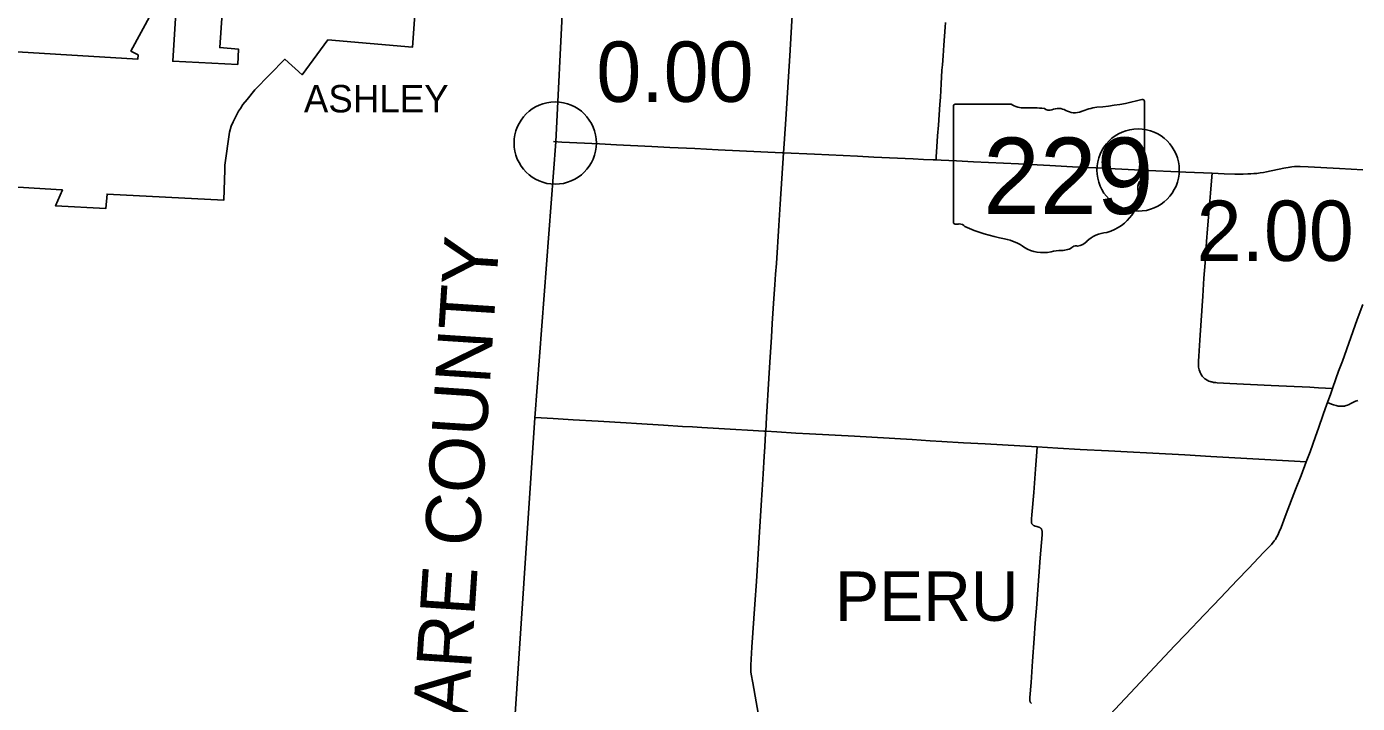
# Model space of a CAD drawing. Extents: x 1813937 to 1948437, y 826606 to 1022856.
# Drawn here: x 1840375 to 1864627, y 867056 to 879389 of the extents above; entities that cross this region are included whole.
import ezdxf

# ---------------------------------------------------------------- set-up
doc = ezdxf.new("R2010")
doc.units = 0
for name, color, linetype in [('Default', 7, 'Continuous'), ('GM_X_Adjacent_County_Text', 7, 'Continuous'), ('GM_X_Corporation', 7, 'Continuous'), ('GM_X_Corporation_Text', 7, 'Continuous'), ('GM_X_County', 7, 'Continuous'), ('GM_X_County_Road', 7, 'Continuous'), ('GM_X_State_Route', 7, 'Continuous'), ('GM_X_State_Shield', 7, 'Continuous'), ('GM_X_Township_Road', 7, 'Continuous'), ('GM_X_Township_Text', 7, 'Continuous')]:
    doc.layers.add(name, color=color, linetype=linetype)

msp = doc.modelspace()

# ---------------------------------------------------------------- linework, layer by layer
at = {"layer": 'Default'}
for centre in [(1850008, 877268), (1850008, 877268), (1860631, 876776)]:
    msp.add_circle(centre, 750, dxfattribs=at)
at = {"layer": 'GM_X_Corporation'}
for points in [[(1839395, 878979), (1842403, 878797), (1842406, 878874), (1842276, 878944), (1843026, 880333)], [(1843137, 880326), (1843037, 878758), (1844222, 878701), (1844237, 878976), (1843894, 879006), (1843983, 880269)], [(1847478, 880034), (1847407, 879013), (1845866, 879149), (1845394, 878513), (1845080, 878796), (1844533, 878238), (1844393, 878064), (1844314, 877970), (1844271, 877898), (1844236, 877846), (1844178, 877730), (1844140, 877653), (1844101, 877578), (1844075, 877468), (1843989, 876865), (1843985, 876781), (1843972, 876227), (1841843, 876336), (1841816, 876073), (1840902, 876121), (1841027, 876414), (1840914, 876421), (1839212, 876522)]]:
    msp.add_lwpolyline(points, dxfattribs=at)
at = {"layer": 'GM_X_County'}
msp.add_lwpolyline([(1849106, 864311), (1849634, 872258), (1850017, 877290), (1850147, 879854), (1845959, 880135), (1842150, 880416), (1839410, 880574)], dxfattribs=at)
at = {"layer": 'GM_X_County_Road'}
for points in [[(1853845, 872014), (1853859, 872274), (1853901, 872979), (1853919, 873274), (1853948, 873731), (1853964, 873978), (1853994, 874436), (1854011, 874682), (1854025, 874878), (1854038, 875075), (1854084, 875763), (1854110, 876156), (1854170, 877091)], [(1864174, 872796), (1864234, 872970), (1864284, 873109), (1864353, 873293), (1864625, 874049), (1864725, 874327)], [(1864084, 872541), (1864143, 872706), (1864174, 872796)], [(1863695, 871458), (1863764, 871641), (1863814, 871779), (1863864, 871918), (1863919, 872073), (1864005, 872320), (1864071, 872506), (1864084, 872541)], [(1853831, 866184), (1853607, 867428), (1853581, 867590), (1853575, 867628), (1853573, 867652), (1853572, 867674), (1853571, 867703), (1853573, 867754), (1853594, 868081), (1853649, 868867), (1853675, 869277), (1853717, 869981), (1853760, 870669), (1853779, 870948), (1853798, 871242), (1853817, 871553), (1853828, 871734), (1853843, 871979), (1853845, 872014)], [(1860116, 866845), (1860675, 867445), (1860843, 867625), (1861293, 868102), (1861498, 868315), (1861837, 868671), (1861996, 868837), (1862132, 868979), (1862437, 869300), (1862641, 869514), (1862923, 869812), (1863059, 869954), (1863111, 870016), (1863132, 870043), (1863148, 870070), (1863161, 870091), (1863176, 870121), (1863203, 870181), (1863235, 870263), (1863312, 870462), (1863441, 870798), (1863501, 870951), (1863602, 871211), (1863695, 871458)]]:
    msp.add_lwpolyline(points, dxfattribs=at)
at = {"layer": 'GM_X_State_Route'}
for points in [[(1849978, 877293), (1850128, 877285), (1850816, 877251), (1851127, 877236), (1851766, 877203), (1852094, 877189), (1852553, 877166), (1852979, 877146), (1854142, 877092), (1854170, 877091), (1854732, 877063), (1855518, 877026), (1855813, 877013), (1856534, 876978), (1856719, 876970)], [(1856719, 876970), (1856895, 876961), (1856952, 876959), (1857042, 876955), (1857321, 876944), (1857632, 876927), (1858451, 876887), (1859025, 876856), (1859434, 876835), (1859860, 876814), (1860450, 876786), (1860679, 876775), (1861499, 876738), (1861978, 876716), (1862196, 876705), (1862395, 876698), (1862473, 876700), (1862543, 876701), (1862632, 876704), (1862686, 876706), (1862740, 876711), (1862796, 876715), (1862854, 876723), (1862916, 876731), (1862968, 876741), (1863289, 876810), (1863401, 876830), (1863435, 876835), (1863483, 876838), (1863519, 876839), (1863581, 876840), (1863728, 876836), (1864301, 876803), (1864727, 876779)]]:
    msp.add_lwpolyline(points, dxfattribs=at)
at = {"layer": 'GM_X_State_Shield'}
for p, q in [((1857265, 877938), (1857265, 875825)), ((1858318, 877975), (1857299, 877975)), ((1860745, 876922), (1860745, 878027)), ((1860745, 876922), (1860745, 876922))]:
    msp.add_line(p, q, dxfattribs=at)
for centre, major_axis, start_param, end_param in [((1857305, 877943), (40.3, 0), 1.712693, 3.28349), ((1858561, 878220), (391, 0), 4.042523, 4.731795), ((1858691, 876788), (1404, 0), 1.404758, 1.657858), ((1859175, 877710), (235, 0), 0.950623, 2.079405), ((1859976, 877329), (743, 0), 1.699011, 2.107814), ((1859505, 880856), (3691, 0), 4.814394, 5.042369), ((1860707, 878032), (38.7, 0), 6.141152, 7.989035), ((1859009, 877954), (113, 0), 3.836095, 5.185415), ((1859478, 878045), (282, 0), 4.081561, 5.145723), ((1860736, 876841), (60, 0), 1.883978, 3.671073), ((1860355, 876701), (360, 0), 5.934695, 6.695948), ((1860704, 876917), (41.5, 0), 5.05454, 6.418171), ((1860884, 876459), (262, 0), 2.387724, 3.262537), ((1859712, 876318), (923, 0), 5.101752, 6.440018), ((1857305, 875821), (40.7, 0), 3.00124, 4.508301), ((1857311, 876037), (310, 0), 4.665946, 4.897461), ((1857375, 875703), (112, 0), 0.519207, 1.627899), ((1858788, 877602), (2665, 0), 4.195997, 4.488961), ((1857993, 874876), (834, 0), 0.823519, 1.323587), ((1860101, 875232), (506, 0), 1.647645, 2.488434), ((1858895, 875693), (529, 0), 4.026481, 4.996735), ((1859201, 874962), (435, 0), 1.495662, 1.94098), ((1859240, 875535), (282, 0), 4.691044, 5.507374), ((1859495, 875330), (79.4, 0), 1.147584, 2.315152), ((1859461, 875620), (298, 0), 4.937069, 5.64225)]:
    msp.add_ellipse(centre, major_axis=major_axis, ratio=0.8, start_param=start_param, end_param=end_param, dxfattribs=at)
at = {"layer": 'GM_X_Township_Road'}
for points in [[(1854170, 877091), (1854181, 877254), (1854216, 877794), (1854258, 878481), (1854281, 878858), (1854321, 879496), (1854345, 879872), (1854397, 880624), (1854480, 881736), (1854531, 882423), (1854534, 882470)], [(1856952, 876959), (1856952, 876988), (1856953, 877021), (1856958, 877103), (1856977, 877398), (1856991, 877595), (1857018, 877972), (1857027, 878102), (1857044, 878348), (1857056, 878594), (1857063, 878692), (1857076, 878856), (1857090, 879053), (1857102, 879216), (1857113, 879380), (1857119, 879462)], [(1861978, 876716), (1861973, 876651), (1861951, 876356), (1861926, 876062), (1861895, 875703), (1861878, 875474), (1861851, 875082), (1861831, 874804), (1861808, 874477), (1861779, 874036), (1861755, 873678), (1861736, 873382), (1861732, 873295), (1861731, 873269), (1861731, 873228), (1861732, 873201), (1861734, 873185), (1861737, 873161), (1861742, 873137), (1861753, 873105), (1861763, 873084), (1861774, 873061), (1861801, 873019), (1861815, 873003), (1861834, 872983), (1861847, 872972), (1861861, 872962), (1861889, 872946), (1861922, 872930), (1861941, 872923), (1861963, 872916), (1861975, 872913), (1861990, 872909), (1862007, 872906), (1862029, 872903), (1862047, 872901), (1862074, 872899), (1862303, 872887), (1863055, 872851), (1863332, 872839), (1863762, 872816), (1863917, 872809), (1864174, 872796)], [(1864084, 872541), (1864126, 872521), (1864145, 872513), (1864157, 872508), (1864172, 872502), (1864194, 872495), (1864217, 872489), (1864241, 872483), (1864274, 872475), (1864300, 872472), (1864324, 872470), (1864350, 872470), (1864374, 872472), (1864391, 872475), (1864406, 872478), (1864425, 872484), (1864446, 872491), (1864475, 872505), (1864498, 872517), (1864571, 872554), (1864594, 872562), (1864616, 872570), (1864634, 872574)], [(1849640, 872268), (1849968, 872248), (1850335, 872225), (1850789, 872198), (1851300, 872168), (1851491, 872156), (1851979, 872125), (1852329, 872103), (1852512, 872093), (1852682, 872085), (1853195, 872053), (1853613, 872026), (1853809, 872016), (1853845, 872014)], [(1853845, 872014), (1854049, 872003), (1854396, 871983), (1854641, 871969), (1855465, 871923), (1855776, 871905), (1856514, 871862), (1856841, 871842), (1857054, 871829), (1857448, 871807), (1857841, 871786), (1858789, 871730)], [(1858789, 871730), (1858783, 871640), (1858763, 871326), (1858730, 870901), (1858694, 870493), (1858688, 870421), (1858687, 870408), (1858686, 870396), (1858685, 870386), (1858685, 870379), (1858685, 870373), (1858685, 870365), (1858685, 870359), (1858686, 870353), (1858687, 870348), (1858689, 870340), (1858692, 870333), (1858695, 870327), (1858700, 870320), (1858705, 870314), (1858710, 870309), (1858716, 870304), (1858722, 870300), (1858728, 870297), (1858734, 870294), (1858738, 870292), (1858746, 870289), (1858751, 870287), (1858763, 870284), (1858788, 870278), (1858802, 870274), (1858811, 870272), (1858816, 870270), (1858821, 870269), (1858826, 870267), (1858835, 870263), (1858838, 870261), (1858842, 870259), (1858846, 870256), (1858851, 870252), (1858856, 870247), (1858859, 870245), (1858862, 870242), (1858865, 870238), (1858868, 870234), (1858871, 870228), (1858873, 870224), (1858876, 870217), (1858879, 870209), (1858881, 870201), (1858881, 870195), (1858882, 870181), (1858882, 870154), (1858880, 870130), (1858846, 869708), (1858778, 868793), (1858757, 868515), (1858739, 868237), (1858709, 867828), (1858680, 867436), (1858659, 867161), (1858658, 867138), (1858657, 867122), (1858657, 867115), (1858657, 867107), (1858658, 867102), (1858660, 867095), (1858662, 867088), (1858665, 867080), (1858667, 867077), (1858669, 867073), (1858673, 867068), (1858678, 867063), (1858684, 867058), (1858690, 867054)], [(1858789, 871730), (1859170, 871708), (1859574, 871685), (1860094, 871660), (1860433, 871642), (1860901, 871616), (1861484, 871584), (1861959, 871558), (1862940, 871500), (1863695, 871458)]]:
    msp.add_lwpolyline(points, dxfattribs=at)

# ---------------------------------------------------------------- texts
at = {"layer": 'Default'}
for s, p in [('0.00', (1850758, 878018)), ('2.00', (1861698, 875119))]:
    msp.add_text(s, height=1100, dxfattribs=at).set_placement(p)
at = {"layer": 'GM_X_Adjacent_County_Text'}
msp.add_text('DELAWARE COUNTY', height=1000, rotation=86.2231, dxfattribs=at).set_placement((1848101, 862036))
at = {"layer": 'GM_X_Corporation_Text'}
msp.add_text('ASHLEY', height=500, rotation=0, dxfattribs=at).set_placement((1845428, 877826))
at = {"layer": 'GM_X_State_Shield'}
msp.add_text('229', height=1392.2, dxfattribs=at).set_placement((1857805, 875974))
at = {"layer": 'GM_X_Township_Text'}
msp.add_text('PERU', height=900, rotation=0, dxfattribs=at).set_placement((1855108, 868560))

doc.saveas('drawing.dxf')
